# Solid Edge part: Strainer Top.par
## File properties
Author: rkriggs
Template: sync iso part.par
Last saved by: plm
Revision: 21
Application: Solid Edge
Density: 913.000 kg/m^3
Accuracy: 0.990
圖檔名稱: Strainer Top
圖檔編號: Strainer Top
major_rev: A
classification: Mechanical/Part
generation: 2
id: D9A5E75256C24E468418997D68A049FC
thumbnail: vault:///?fileId=7F6B16D5C9194348BC1AF1B2037281CE
authoring_tool: Solid Edge
Material: Polypropylene, general purpose
Face Style: Blue
Fill Style: ANSI34(Plastic)
Virtual Style: Green (Shiny)
Coef. of Thermal Exp: 6.8e-05
Thermal Conductivity: 2.1
Specific Heat: 1884.0
Modulus of Elasticity: 1103161120.0
Poisson's Ratio: 0.35
Yield Stress: 33094833.6
Ultimate Stress: 0.0
Elongation: 0.0
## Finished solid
Body 1: solid body, 134 faces, 336 edges, 176 vertices.
  Faces by surface: plane 71, cylinder 54, torus 7, cone 2
  Edges by curve: line 168, circle 112, intersection 56
Bounding box of the edges (mm; curved faces can reach further): 114.357 x 114.357 x 20.574, from (-57.1786, -57.1786, 93.2942) to (57.1786, 57.1786, 113.8682).
Cylindrical faces by radius (mm): R0.254 x8, R0.762 x4, R0.9271 x24, R1.0922 x4, R18.081 x1, R18.843 x1, R52.832 x4, R53.594 x4, R57.5301 x4
Conical faces (half-angle, radius in mm at the cone's reference point): 59.6098 deg R19.05 x1, 59.6098 deg R52.625 x1
Toroidal faces (ring radius, tube radius in mm): R18.335 r0.254 x1, R18.589 r0.254 x1, R19.097 r0.254 x1, R57.2761 r0.254 x4
Planar faces by outward normal: +x 10, +y 10, +z 10, -x 10, -y 10, -z 9, oblique 12
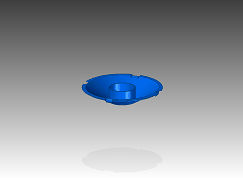
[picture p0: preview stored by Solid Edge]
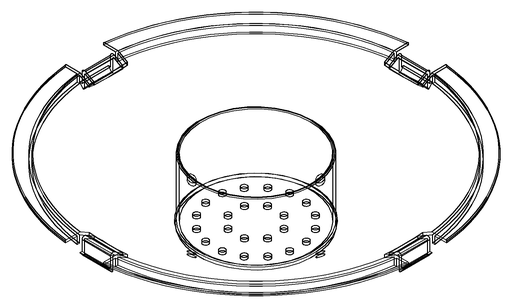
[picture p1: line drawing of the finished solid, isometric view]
